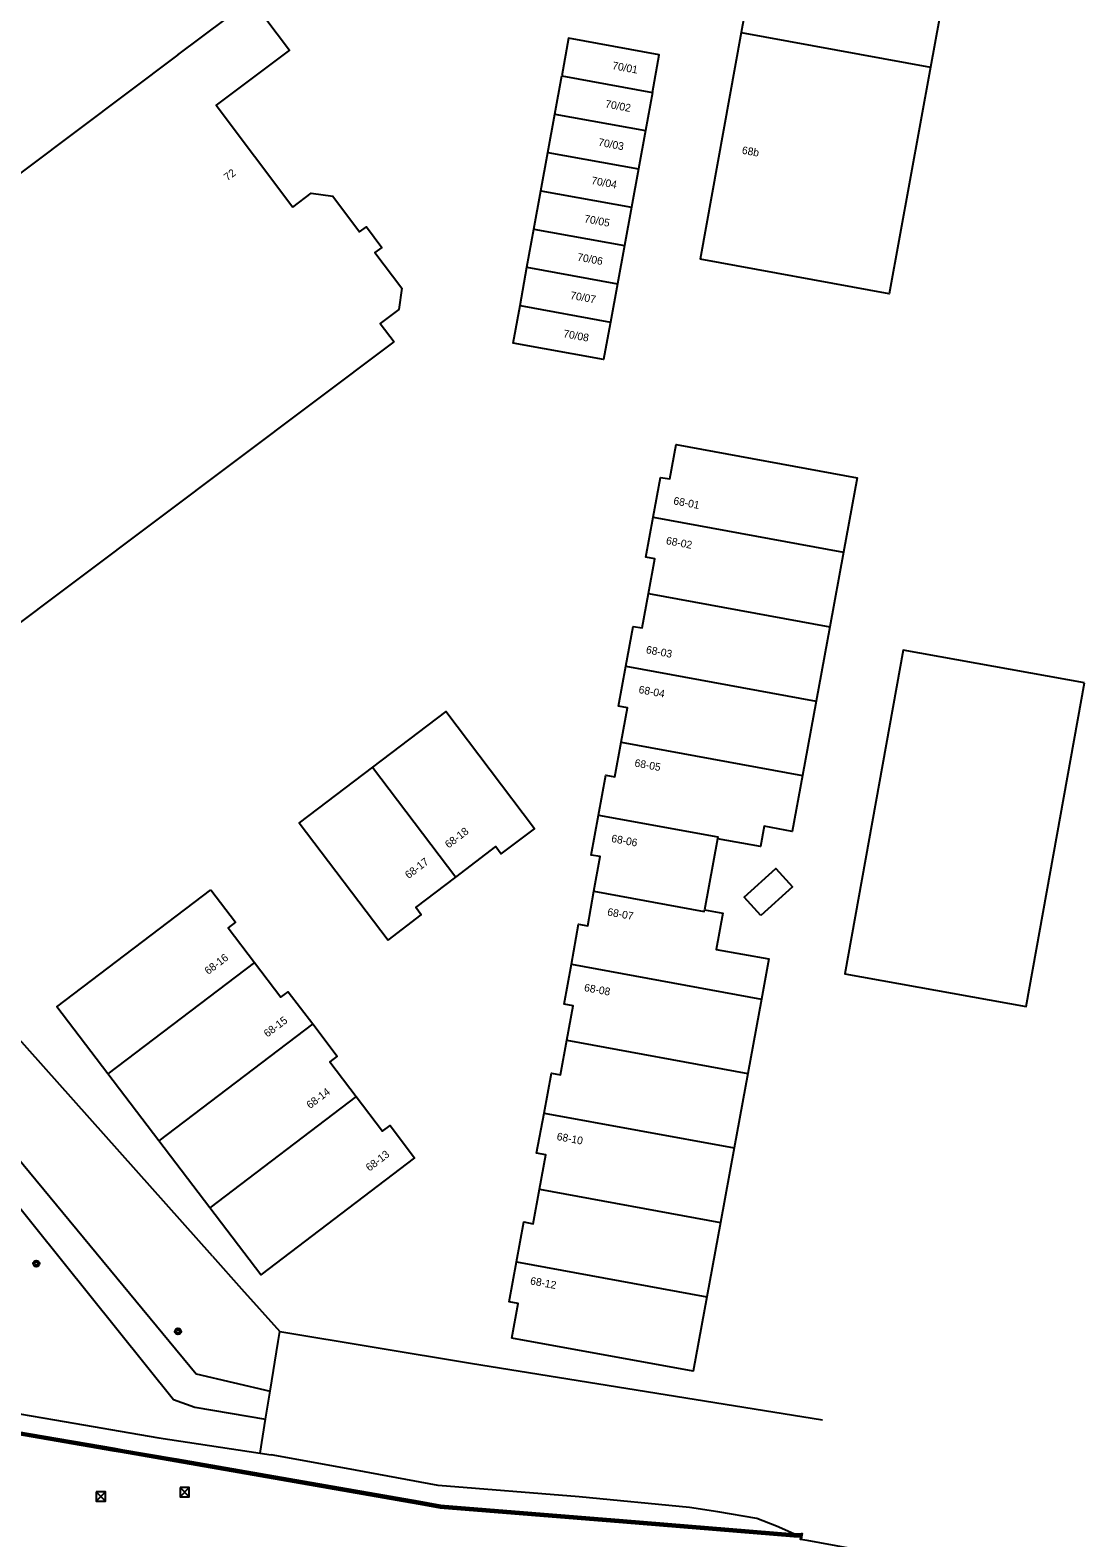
# Model space of a CAD drawing. Extents: x 130998 to 133001, y 398999 to 403002.
# Drawn here: x 131275 to 131412.6, y 399178.7 to 399375.3 of the extents above; entities that cross this region are included whole.
import ezdxf

# ---------------------------------------------------------------- set-up
doc = ezdxf.new("R2010")
doc.units = 0
for name, color, linetype in [('gg-afsc-hekwerk', 7, 'Continuous'), ('gg-afsc-muur', 7, 'Continuous'), ('gg-anno-huisnummerreeks BGT', 7, 'Continuous'), ('gg-bbg-bijgebouw', 7, 'Continuous'), ('gg-bbg-gedigitaliseerde bebouwing', 7, 'Continuous'), ('gg-bbg-hoofdgebouw', 7, 'Continuous'), ('gg-bbg-tussenscheiding', 7, 'Continuous'), ('gg-knt-BGT kruinlijn', 7, 'Continuous'), ('gg-knt-verharding', 7, 'Continuous'), ('gt-symb-boom', 7, 'Continuous'), ('gt-symb-meerpaal', 7, 'Continuous'), ('gx-grn-maaiveld', 7, 'Continuous')]:
    doc.layers.add(name, color=color, linetype=linetype)

# ---------------------------------------------------------------- blocks, each defined once
blk = doc.blocks.new('gt0-BOOM')
at = {"layer": 'gt-symb-boom'}
for radius in [0.4, 0.2]:
    blk.add_circle((0, 0), radius, dxfattribs=at)
blk = doc.blocks.new('gt0-MPAAL')
at = {"layer": 'gt-symb-meerpaal'}
for p, q in [((-0.6, 0.6), (0.6, -0.6)), ((-0.6, -0.6), (0.6, 0.6))]:
    blk.add_line(p, q, dxfattribs=at)
blk.add_lwpolyline([(-0.6, 0.6), (-0.6, -0.6), (0.6, -0.6), (0.6, 0.6)], close=True, dxfattribs=at)

msp = doc.modelspace()

# ---------------------------------------------------------------- linework, layer by layer
at = {"layer": 'gg-afsc-hekwerk'}
for p, q in [((131298.75, 399215.46), (131302.55, 399211.19)), ((131302.55, 399211.19), (131307.52, 399205.61)), ((131307.31, 399204.3), (131307.52, 399205.61)), ((131306.25, 399197.83), (131307.31, 399204.3)), ((131305.66, 399194.2), (131306.25, 399197.83)), ((131304.94, 399189.75), (131305.66, 399194.2)), ((131304.94, 399189.75), (131305.66, 399194.2))]:
    msp.add_line(p, q, dxfattribs=at)
for points in [[(131298.75, 399215.46), (131214.53, 399309.99), (131206.21, 399319.14)], [(131307.52, 399205.61), (131332.39, 399201.48), (131378.22, 399194.11)]]:
    msp.add_lwpolyline(points, dxfattribs=at)
at = {"layer": 'gg-afsc-muur'}
msp.add_lwpolyline([(131375.4, 399179.01), (131374.5, 399179.06), (131352.24, 399180.9), (131328.43, 399182.81), (131325.59, 399183.33), (131304.93, 399186.92), (131293.98, 399188.83), (131286.78, 399190.08), (131285.91, 399190.22), (131273.17, 399192.43), (131258.04, 399194.89), (131256.99, 399194.97), (131256.4, 399194.86), (131255.59, 399194.93), (131238.84, 399197.91), (131237.91, 399197.98)], dxfattribs=at)
at = {"layer": 'gg-bbg-bijgebouw'}
for points in [[(131412.39, 399290.18), (131388.76, 399294.45), (131381.14, 399252.24), (131404.77, 399247.98), (131412.39, 399290.18)], [(131370.2, 399259.84), (131368.02, 399262.25), (131372.14, 399265.99), (131374.33, 399263.58), (131370.2, 399259.84)]]:
    msp.add_lwpolyline(points, dxfattribs=at)
at = {"layer": 'gg-bbg-gedigitaliseerde bebouwing'}
msp.add_line((131397.72, 399400.05), (131392.33, 399370.48), dxfattribs=at)
msp.add_lwpolyline([(131392.33, 399370.48), (131386.93, 399340.91), (131362.3, 399345.46)], dxfattribs=at)
at = {"layer": 'gg-bbg-hoofdgebouw'}
for p, q in [((131373.04, 399404.55), (131367.66, 399374.98)), ((131367.66, 399374.98), (131362.3, 399345.46)), ((131343.36, 399364.35), (131344.27, 399369.34)), ((131356.07, 399367.19), (131355.16, 399362.2)), ((131342.45, 399359.36), (131343.36, 399364.35)), ((131355.16, 399362.2), (131354.24, 399357.2)), ((131341.54, 399354.36), (131342.45, 399359.36)), ((131354.24, 399357.2), (131353.33, 399352.21)), ((131340.64, 399349.37), (131341.54, 399354.36)), ((131353.33, 399352.21), (131352.42, 399347.22)), ((131339.73, 399344.38), (131340.64, 399349.37)), ((131352.42, 399347.22), (131351.51, 399342.22)), ((131338.82, 399339.38), (131339.73, 399344.38)), ((131351.51, 399342.22), (131350.6, 399337.23)), ((131380.97, 399307.23), (131379.19, 399297.52)), ((131379.19, 399297.52), (131377.4, 399287.82)), ((131377.4, 399287.82), (131375.62, 399278.11)), ((131364.56, 399269.87), (131362.86, 399260.61)), ((131370.27, 399248.97), (131368.49, 399239.27)), ((131291.76, 399230.47), (131285.11, 399239.2)), ((131368.49, 399239.27), (131366.71, 399229.56)), ((131298.4, 399221.73), (131291.76, 399230.47)), ((131366.71, 399229.56), (131364.93, 399219.85)), ((131364.93, 399219.85), (131363.15, 399210.15))]:
    msp.add_line(p, q, dxfattribs=at)
for points in [[(131294.23, 399372.1), (131303.81, 399379.31), (131308.78, 399372.7), (131299.22, 399365.5), (131309.21, 399352.23)], [(131356.07, 399367.19), (131356.96, 399372.09), (131345.16, 399374.24), (131344.27, 399369.34)], [(131294.23, 399372.1), (131221.96, 399317.77), (131250.13, 399280.36), (131322.41, 399334.65)], [(131309.21, 399352.23), (131311.62, 399354.04), (131314.42, 399353.65), (131317.92, 399349.02), (131318.82, 399349.67), (131320.81, 399346.98), (131319.92, 399346.32), (131323.43, 399341.67), (131323.02, 399338.88), (131320.61, 399337.07), (131322.41, 399334.65)], [(131350.6, 399337.23), (131349.92, 399333.52), (131349.71, 399332.34), (131337.93, 399334.49), (131338.82, 399339.38)], [(131356.19, 399311.78), (131357.15, 399316.98), (131358.33, 399316.78), (131359.15, 399321.27), (131382.75, 399316.93), (131380.97, 399307.23)], [(131355.58, 399301.86), (131356.41, 399306.36), (131355.22, 399306.58), (131356.19, 399311.78)], [(131352.61, 399292.37), (131353.57, 399297.56), (131354.75, 399297.35), (131355.58, 399301.86)], [(131352.01, 399282.45), (131352.83, 399286.96), (131351.65, 399287.17), (131352.61, 399292.37)], [(131330.45, 399264.88), (131335.66, 399268.86), (131336.38, 399267.9), (131340.73, 399271.17), (131329.14, 399286.44), (131319.58, 399279.19)], [(131349.05, 399272.95), (131350.02, 399278.15), (131351.19, 399277.94), (131352.01, 399282.45)], [(131319.58, 399279.19), (131310.03, 399271.94), (131321.64, 399256.66)], [(131375.62, 399278.11), (131374.29, 399270.83), (131370.65, 399271.5), (131370.16, 399268.84), (131364.56, 399269.87)], [(131348.46, 399263.02), (131349.28, 399267.54), (131348.1, 399267.75), (131349.05, 399272.95)], [(131321.64, 399256.66), (131325.96, 399259.96), (131325.23, 399260.91), (131330.45, 399264.88)], [(131285.11, 399239.2), (131278.47, 399247.94), (131298.53, 399263.2)], [(131298.53, 399263.2), (131301.73, 399258.99), (131300.77, 399258.26), (131304.21, 399253.73)], [(131345.51, 399253.51), (131346.46, 399258.72), (131347.64, 399258.5), (131348.46, 399263.02)], [(131362.86, 399260.61), (131365.25, 399260.17), (131364.38, 399255.45), (131371.23, 399254.2), (131370.27, 399248.97)], [(131304.21, 399253.73), (131307.66, 399249.2), (131308.62, 399249.93), (131311.81, 399245.72)], [(131344.91, 399243.59), (131345.74, 399248.09), (131344.56, 399248.31), (131345.51, 399253.51)], [(131311.81, 399245.72), (131315, 399241.5), (131314.04, 399240.77), (131317.48, 399236.25)], [(131341.95, 399234.1), (131342.91, 399239.31), (131344.09, 399239.1), (131344.91, 399243.59)], [(131317.48, 399236.25), (131320.92, 399231.73), (131321.88, 399232.46), (131325.09, 399228.28), (131305.03, 399213.02), (131298.4, 399221.73)], [(131341.34, 399224.18), (131342.17, 399228.67), (131340.99, 399228.89), (131341.95, 399234.1)], [(131338.38, 399214.7), (131339.34, 399219.9), (131340.52, 399219.68), (131341.34, 399224.18)], [(131337.77, 399204.77), (131338.59, 399209.28), (131337.41, 399209.49), (131338.38, 399214.7)], [(131363.15, 399210.15), (131361.37, 399200.44), (131337.77, 399204.77)]]:
    msp.add_lwpolyline(points, dxfattribs=at)
at = {"layer": 'gg-bbg-tussenscheiding'}
for p, q in [((131367.66, 399374.98), (131392.33, 399370.48)), ((131344.27, 399369.34), (131356.07, 399367.19)), ((131343.36, 399364.35), (131355.16, 399362.2)), ((131342.45, 399359.36), (131354.24, 399357.2)), ((131341.54, 399354.36), (131353.33, 399352.21)), ((131340.64, 399349.37), (131352.42, 399347.22)), ((131339.73, 399344.38), (131351.51, 399342.22)), ((131338.82, 399339.38), (131350.6, 399337.23)), ((131356.19, 399311.78), (131380.97, 399307.23)), ((131355.58, 399301.86), (131379.19, 399297.52)), ((131352.61, 399292.37), (131377.4, 399287.82)), ((131352.01, 399282.45), (131375.62, 399278.11)), ((131319.58, 399279.19), (131330.45, 399264.88)), ((131304.21, 399253.73), (131285.11, 399239.2)), ((131345.51, 399253.51), (131370.27, 399248.97)), ((131311.81, 399245.72), (131291.76, 399230.47)), ((131344.91, 399243.59), (131368.49, 399239.27)), ((131317.48, 399236.25), (131298.4, 399221.73)), ((131341.95, 399234.1), (131366.71, 399229.56)), ((131341.34, 399224.18), (131364.93, 399219.85)), ((131338.38, 399214.7), (131363.15, 399210.15))]:
    msp.add_line(p, q, dxfattribs=at)
for points in [[(131349.05, 399272.95), (131364.6, 399270.1), (131364.56, 399269.87)], [(131348.46, 399263.02), (131362.82, 399260.39), (131362.86, 399260.61)]]:
    msp.add_lwpolyline(points, dxfattribs=at)
at = {"layer": 'gg-knt-BGT kruinlijn'}
for p, q in [((131265.69, 399196.27), (131278.15, 399194.09)), ((131278.15, 399194.09), (131291.74, 399191.76)), ((131291.74, 399191.76), (131304.94, 399189.75)), ((131304.94, 399189.75), (131306.38, 399189.53)), ((131316.21, 399187.74), (131306.38, 399189.53)), ((131328.17, 399185.54), (131316.21, 399187.74)), ((131346.52, 399184.06), (131328.17, 399185.54)), ((131360.9, 399182.69), (131346.52, 399184.06)), ((131364.59, 399182.09), (131360.9, 399182.69)), ((131369.68, 399181.24), (131364.59, 399182.09)), ((131372.24, 399180.22), (131369.68, 399181.24)), ((131374.52, 399179.24), (131372.24, 399180.22))]:
    msp.add_line(p, q, dxfattribs=at)
at = {"layer": 'gg-knt-verharding'}
for points in [[(131164.38, 399343.97), (131179.93, 399330.8), (131190.98, 399321.2), (131203.16, 399311.08), (131208.78, 399305.86), (131222.96, 399289.26), (131296.62, 399200.12), (131306.25, 399197.83)], [(131163.01, 399342.29), (131178.47, 399329.02), (131189.45, 399319.58), (131200.78, 399309.88), (131207.27, 399304.2), (131220.83, 399287.61), (131293.65, 399196.74), (131296.45, 399195.74), (131305.66, 399194.2)]]:
    msp.add_lwpolyline(points, dxfattribs=at)
at = {"layer": 'gx-grn-maaiveld'}
for p, q in [((131375.48, 399179.18), (131374.52, 399179.24)), ((131375.42, 399178.83), (131375.48, 399179.18))]:
    msp.add_line(p, q, dxfattribs=at)
for points in [[(131237.6, 399197.83), (131237.7, 399197.82), (131238.82, 399197.74), (131255.57, 399194.75), (131256.41, 399194.69), (131257, 399194.79), (131258.02, 399194.71), (131273.14, 399192.26), (131285.88, 399190.05), (131286.75, 399189.91), (131293.95, 399188.66), (131304.9, 399186.74), (131325.56, 399183.16), (131328.41, 399182.63), (131352.22, 399180.72), (131374.49, 399178.89), (131375.42, 399178.83)], [(131257.81, 399195.08), (131258.06, 399195.06), (131273.2, 399192.6), (131285.94, 399190.39), (131286.81, 399190.25), (131294.01, 399189), (131304.96, 399187.09), (131325.62, 399183.51), (131328.45, 399182.98), (131352.25, 399181.07), (131374.52, 399179.24)], [(131514.83, 399153.28), (131497.57, 399156.46), (131466.05, 399162.07), (131436.52, 399167.45), (131411.91, 399171.9), (131399.66, 399174.11), (131389.24, 399175.98), (131376.24, 399178.36), (131375.36, 399178.52), (131375.42, 399178.83)], [(131375.48, 399179.18), (131375.5, 399179.3), (131375.61, 399179.28), (131375.48, 399178.6)]]:
    msp.add_lwpolyline(points, dxfattribs=at)

# ---------------------------------------------------------------- block references
at = {"layer": 'gt-symb-boom'}
for p in [(131275.79, 399214.47), (131294.25, 399205.64)]:
    msp.add_blockref('gt0-BOOM', p, dxfattribs=at)
at = {"layer": 'gt-symb-meerpaal'}
for p in [(131284.19, 399184.1), (131295.12, 399184.68)]:
    msp.add_blockref('gt0-MPAAL', p, dxfattribs=at)

# ---------------------------------------------------------------- texts
at = {"layer": 'gg-anno-huisnummerreeks BGT'}
for s, rotation, p in [('70/01', 349.6, (131350.78, 399370.23)), ('70/02', 349.7, (131349.87, 399365.23)), ('70/03', 349.6, (131348.96, 399360.24)), ('68b', 349.7, (131367.68, 399359.2)), ('72', 37, (131300.7, 399355.59)), ('70/04', 349.7, (131348.05, 399355.24)), ('70/05', 349.6, (131347.13, 399350.26)), ('70/06', 349.7, (131346.22, 399345.26)), ('70/07', 349.6, (131345.31, 399340.27)), ('70/08', 349.6, (131344.4, 399335.28)), ('68-01', 349.5, (131358.75, 399313.49)), ('68-02', 349.5, (131357.79, 399308.29)), ('68-03', 349.5, (131355.18, 399294.07)), ('68-04', 349.5, (131354.22, 399288.88)), ('68-05', 349.7, (131353.69, 399279.3)), ('68-18', 37.3, (131329.51, 399268.57)), ('68-06', 349.5, (131350.66, 399269.46)), ('68-17', 37.3, (131324.3, 399264.6)), ('68-07', 349.7, (131350.14, 399259.88)), ('68-16', 37.2, (131298.19, 399252.1)), ('68-08', 349.7, (131347.12, 399250.02)), ('68-15', 37.1, (131305.9, 399243.93)), ('68-14', 37.3, (131311.46, 399234.61)), ('68-10', 349.6, (131343.55, 399230.6)), ('68-13', 37.5, (131319.2, 399226.45)), ('68-12', 349.5, (131340.09, 399211.78))]:
    msp.add_text(s, height=1, rotation=rotation, dxfattribs=at).set_placement(p)

doc.saveas('drawing.dxf')
